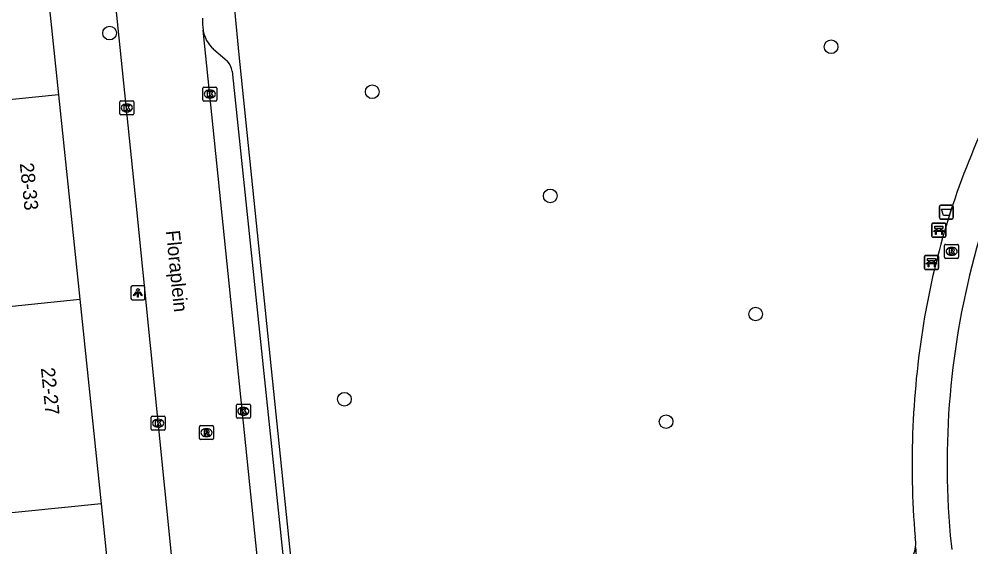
# Model space of a CAD drawing. Extents: x 162250 to 162654, y 380744 to 381605.
# Drawn here: x 162546.8 to 162615, y 380793.8 to 380831.6 of the extents above; entities that cross this region are included whole.
import ezdxf

# ---------------------------------------------------------------- set-up
doc = ezdxf.new("R2010")
doc.units = 0
for name, color, linetype in [('IMGEO_Afvalbak', 7, 'Continuous'), ('IMGEO_Bank', 7, 'Continuous'), ('IMGEO_Boom', 7, 'Continuous'), ('IMGEO_Fietspad_gesloten', 7, 'Continuous'), ('IMGEO_Kolk', 7, 'Continuous'), ('IMGEO_Lichtpunt', 7, 'Continuous'), ('IMGEO_Openbare_ruimte_label', 7, 'Continuous'), ('IMGEO_Pand', 7, 'Continuous'), ('IMGEO_Pand_nummerreeks', 7, 'Continuous'), ('IMGEO_Rijbaan_lokaal_open', 7, 'Continuous'), ('IMGEO_Rioolput', 7, 'Continuous'), ('IMGEO_Voetpad_open', 7, 'Continuous')]:
    doc.layers.add(name, color=color, linetype=linetype)

msp = doc.modelspace()

# ---------------------------------------------------------------- linework, layer by layer
at = {"layer": 'IMGEO_Afvalbak'}
for p, q in [((162612.693, 380817.38), (162612.693, 380818.18)), ((162612.693, 380818.18), (162612.693, 380817.38)), ((162612.793, 380818.28), (162613.583, 380818.28)), ((162613.583, 380818.28), (162612.793, 380818.28)), ((162613.683, 380818.18), (162613.683, 380817.38)), ((162613.683, 380817.38), (162613.683, 380818.18)), ((162613.583, 380817.28), (162612.793, 380817.28)), ((162612.793, 380817.28), (162613.583, 380817.28))]:
    msp.add_line(p, q, dxfattribs=at)
msp.add_lwpolyline([(162612.836, 380817.994), (162613.54, 380817.994), (162613.391, 380817.524), (162612.985, 380817.524), (162612.836, 380817.994)], dxfattribs=at)
for centre, start, end in [((162612.793, 380818.18), 90, 180), ((162612.793, 380818.18), 90, 180), ((162613.583, 380818.18), 0, 90), ((162613.583, 380818.18), 360, 90), ((162612.793, 380817.38), 180, 270), ((162612.793, 380817.38), 180, 270), ((162613.583, 380817.38), 270, 0), ((162613.583, 380817.38), 270, 0)]:
    msp.add_arc(centre, 0.1, start, end, dxfattribs=at)
at = {"layer": 'IMGEO_Bank'}
for p, q in [((162612.153, 380816.06), (162612.153, 380816.901)), ((162612.153, 380816.901), (162612.153, 380816.06)), ((162612.228, 380816.985), (162613.069, 380816.985)), ((162613.069, 380816.985), (162612.228, 380816.985)), ((162613.153, 380816.91), (162613.153, 380816.069)), ((162613.153, 380816.069), (162613.153, 380816.91)), ((162612.85, 380816.383), (162612.457, 380816.383)), ((162612.462, 380816.491), (162612.462, 380816.597)), ((162612.506, 380816.597), (162612.506, 380816.491)), ((162612.794, 380816.603), (162612.512, 380816.603)), ((162612.512, 380816.485), (162612.794, 380816.485)), ((162612.8, 380816.491), (162612.8, 380816.597)), ((162612.844, 380816.597), (162612.844, 380816.491)), ((162613.078, 380815.985), (162612.237, 380815.985)), ((162612.237, 380815.985), (162613.078, 380815.985)), ((162611.627, 380813.752), (162611.627, 380814.593)), ((162611.627, 380814.593), (162611.627, 380813.752)), ((162611.702, 380814.677), (162612.543, 380814.677)), ((162612.543, 380814.677), (162611.702, 380814.677)), ((162612.324, 380814.075), (162611.931, 380814.075)), ((162611.936, 380814.183), (162611.936, 380814.289)), ((162611.98, 380814.289), (162611.98, 380814.183)), ((162612.268, 380814.295), (162611.986, 380814.295)), ((162611.986, 380814.177), (162612.268, 380814.177)), ((162612.274, 380814.183), (162612.274, 380814.289)), ((162612.318, 380814.289), (162612.318, 380814.183)), ((162612.627, 380814.602), (162612.627, 380813.761)), ((162612.627, 380813.761), (162612.627, 380814.602)), ((162612.552, 380813.677), (162611.711, 380813.677)), ((162611.711, 380813.677), (162612.552, 380813.677))]:
    msp.add_line(p, q, dxfattribs=at)
for points in [[(162612.4, 380816.383), (162612.258, 380816.383), (162612.37, 380816.485), (162612.456, 380816.485)], [(162612.456, 380816.603), (162612.37, 380816.603), (162612.37, 380816.764), (162612.933, 380816.764), (162612.933, 380816.603), (162612.85, 380816.603)], [(162612.45, 380816.376), (162612.45, 380816.169), (162612.407, 380816.169), (162612.407, 380816.376)], [(162612.85, 380816.485), (162612.933, 380816.485), (162613.045, 380816.383), (162612.906, 380816.383)], [(162612.9, 380816.376), (162612.9, 380816.169), (162612.856, 380816.169), (162612.856, 380816.376)], [(162611.874, 380814.075), (162611.732, 380814.075), (162611.844, 380814.177), (162611.93, 380814.177)], [(162611.93, 380814.295), (162611.844, 380814.295), (162611.844, 380814.456), (162612.407, 380814.456), (162612.407, 380814.295), (162612.324, 380814.295)], [(162611.924, 380814.068), (162611.924, 380813.861), (162611.881, 380813.861), (162611.881, 380814.068)], [(162612.324, 380814.177), (162612.407, 380814.177), (162612.519, 380814.075), (162612.38, 380814.075)], [(162612.374, 380814.068), (162612.374, 380813.861), (162612.33, 380813.861), (162612.33, 380814.068)]]:
    msp.add_lwpolyline(points, dxfattribs=at)
for centre, radius, start, end in [((162612.231, 380816.907), 0.0779, 92.4484, 184.28452), ((162612.231, 380816.907), 0.0779, 92.4484, 184.28452), ((162613.075, 380816.907), 0.0779, 2.4484, 94.28452), ((162613.075, 380816.907), 0.0779, 2.4484, 94.28452), ((162612.4, 380816.376), 0.00671, 2.89567, 87.10433), ((162612.457, 380816.376), 0.00671, 92.89567, 177.10433), ((162612.455, 380816.596), 0.00671, 2.89567, 87.10433), ((162612.455, 380816.492), 0.00671, 272.89567, 357.10433), ((162612.512, 380816.596), 0.00671, 92.89567, 177.10433), ((162612.512, 380816.492), 0.00671, 182.89567, 267.10433), ((162612.794, 380816.596), 0.00671, 2.89567, 87.10433), ((162612.794, 380816.492), 0.00671, 272.89567, 357.10433), ((162612.851, 380816.596), 0.00671, 92.89567, 177.10433), ((162612.851, 380816.492), 0.00671, 182.89567, 267.10433), ((162612.849, 380816.376), 0.00671, 2.89567, 87.10433), ((162612.906, 380816.376), 0.00671, 92.89567, 177.10433), ((162612.231, 380816.063), 0.0779, 182.4484, 274.28452), ((162612.231, 380816.063), 0.0779, 182.4484, 274.28452), ((162613.075, 380816.063), 0.0779, 272.4484, 4.28452), ((162613.075, 380816.063), 0.0779, 272.4484, 4.28452), ((162611.705, 380814.599), 0.0779, 92.4484, 184.28452), ((162611.705, 380814.599), 0.0779, 92.4484, 184.28452), ((162611.874, 380814.068), 0.00671, 2.89567, 87.10433), ((162611.931, 380814.068), 0.00671, 92.89567, 177.10433), ((162611.929, 380814.288), 0.00671, 2.89567, 87.10433), ((162611.929, 380814.184), 0.00671, 272.89567, 357.10433), ((162611.986, 380814.288), 0.00671, 92.89567, 177.10433), ((162611.986, 380814.184), 0.00671, 182.89567, 267.10433), ((162612.268, 380814.288), 0.00671, 2.89567, 87.10433), ((162612.268, 380814.184), 0.00671, 272.89567, 357.10433), ((162612.325, 380814.288), 0.00671, 92.89567, 177.10433), ((162612.325, 380814.184), 0.00671, 182.89567, 267.10433), ((162612.323, 380814.068), 0.00671, 2.89567, 87.10433), ((162612.38, 380814.068), 0.00671, 92.89567, 177.10433), ((162612.549, 380814.599), 0.0779, 2.4484, 94.28452), ((162612.549, 380814.599), 0.0779, 2.4484, 94.28452), ((162611.705, 380813.755), 0.0779, 182.4484, 274.28452), ((162611.705, 380813.755), 0.0779, 182.4484, 274.28452), ((162612.549, 380813.755), 0.0779, 272.4484, 4.28452), ((162612.549, 380813.755), 0.0779, 272.4484, 4.28452)]:
    msp.add_arc(centre, radius, start, end, dxfattribs=at)
at = {"layer": 'IMGEO_Boom'}
for centre in [(162553.294, 380830.584), (162604.942, 380829.605), (162572.094, 380826.386), (162584.831, 380818.936), (162599.539, 380810.487), (162570.107, 380804.394), (162593.129, 380802.787)]:
    msp.add_circle(centre, 0.489, dxfattribs=at)
at = {"layer": 'IMGEO_Fietspad_gesloten'}
msp.add_lwpolyline([(162613.473, 380794.639), (162613.577, 380793.648)], dxfattribs=at)
msp.add_arc((162670.749, 380799.765), 57.505, 163.75865, 185.11392, dxfattribs=at)
at = {"layer": 'IMGEO_Kolk'}
for p, q in [((162559.968, 380825.795), (162559.968, 380826.647)), ((162560.043, 380826.721), (162560.895, 380826.721)), ((162560.456, 380826.501), (162560.481, 380826.501)), ((162560.969, 380826.647), (162560.969, 380825.795)), ((162554.023, 380824.802), (162554.023, 380825.654)), ((162554.098, 380825.728), (162554.95, 380825.728)), ((162555.024, 380825.654), (162555.024, 380824.802)), ((162560.895, 380825.721), (162560.043, 380825.721)), ((162560.479, 380825.941), (162560.454, 380825.941)), ((162554.511, 380825.508), (162554.536, 380825.508)), ((162554.95, 380824.728), (162554.098, 380824.728)), ((162554.534, 380824.948), (162554.509, 380824.948)), ((162562.366, 380803.104), (162562.366, 380803.956)), ((162562.441, 380804.03), (162563.293, 380804.03)), ((162563.367, 380803.956), (162563.367, 380803.104)), ((162556.342, 380803.175), (162557.194, 380803.175)), ((162562.877, 380803.25), (162562.852, 380803.25)), ((162562.854, 380803.81), (162562.879, 380803.81)), ((162556.267, 380802.249), (162556.267, 380803.101)), ((162556.755, 380802.955), (162556.78, 380802.955)), ((162557.268, 380803.101), (162557.268, 380802.249)), ((162563.293, 380803.03), (162562.441, 380803.03)), ((162557.194, 380802.175), (162556.342, 380802.175)), ((162556.778, 380802.395), (162556.753, 380802.395))]:
    msp.add_line(p, q, dxfattribs=at)
for points in [[(162559.968, 380825.795), (162559.968, 380826.647)], [(162560.043, 380826.721), (162560.895, 380826.721)], [(162560.289, 380826.421), (162560.412, 380826.421), (162560.412, 380826.27), (162560.542, 380826.421), (162560.706, 380826.421), (162560.56, 380826.27), (162560.713, 380826.021), (162560.561, 380826.021), (162560.476, 380826.185), (162560.412, 380826.118), (162560.412, 380826.021), (162560.289, 380826.021), (162560.289, 380826.421)], [(162560.969, 380826.647), (162560.969, 380825.795)], [(162554.023, 380824.802), (162554.023, 380825.654)], [(162554.098, 380825.728), (162554.95, 380825.728)], [(162555.024, 380825.654), (162555.024, 380824.802)], [(162560.895, 380825.721), (162560.043, 380825.721)], [(162554.344, 380825.428), (162554.467, 380825.428), (162554.467, 380825.277), (162554.597, 380825.428), (162554.761, 380825.428), (162554.615, 380825.277), (162554.768, 380825.028), (162554.616, 380825.028), (162554.531, 380825.192), (162554.467, 380825.125), (162554.467, 380825.028), (162554.344, 380825.028), (162554.344, 380825.428)], [(162554.95, 380824.728), (162554.098, 380824.728)], [(162562.366, 380803.104), (162562.366, 380803.956)], [(162562.441, 380804.03), (162563.293, 380804.03)], [(162563.367, 380803.956), (162563.367, 380803.104)], [(162556.342, 380803.175), (162557.194, 380803.175)], [(162562.687, 380803.73), (162562.81, 380803.73), (162562.81, 380803.579), (162562.94, 380803.73), (162563.104, 380803.73), (162562.958, 380803.579), (162563.111, 380803.33), (162562.959, 380803.33), (162562.874, 380803.494), (162562.81, 380803.427), (162562.81, 380803.33), (162562.687, 380803.33), (162562.687, 380803.73)], [(162556.267, 380802.249), (162556.267, 380803.101)], [(162556.588, 380802.875), (162556.711, 380802.875), (162556.711, 380802.724), (162556.841, 380802.875), (162557.005, 380802.875), (162556.859, 380802.724), (162557.012, 380802.475), (162556.86, 380802.475), (162556.775, 380802.639), (162556.711, 380802.572), (162556.711, 380802.475), (162556.588, 380802.475), (162556.588, 380802.875)], [(162557.268, 380803.101), (162557.268, 380802.249)], [(162563.293, 380803.03), (162562.441, 380803.03)], [(162557.194, 380802.175), (162556.342, 380802.175)]]:
    msp.add_lwpolyline(points, dxfattribs=at)
for centre, start, end in [((162560.045, 380826.645), 91.55205, 178.44795), ((162560.045, 380826.645), 91.55205, 178.44795), ((162560.893, 380826.645), 1.55205, 88.44795), ((162560.893, 380826.645), 1.55205, 88.44795), ((162554.1, 380825.652), 91.55205, 178.44795), ((162554.1, 380825.652), 91.55205, 178.44795), ((162554.948, 380825.652), 1.55205, 88.44795), ((162554.948, 380825.652), 1.55205, 88.44795), ((162560.045, 380825.797), 181.55205, 268.44795), ((162560.045, 380825.797), 181.55205, 268.44795), ((162560.893, 380825.797), 271.55205, 358.44795), ((162560.893, 380825.797), 271.55205, 358.44795), ((162554.1, 380824.804), 181.55205, 268.44795), ((162554.1, 380824.804), 181.55205, 268.44795), ((162554.948, 380824.804), 271.55205, 358.44795), ((162554.948, 380824.804), 271.55205, 358.44795), ((162562.443, 380803.954), 91.55205, 178.44795), ((162562.443, 380803.954), 91.55205, 178.44795), ((162563.291, 380803.954), 1.55205, 88.44795), ((162563.291, 380803.954), 1.55205, 88.44795), ((162556.344, 380803.099), 91.55205, 178.44795), ((162556.344, 380803.099), 91.55205, 178.44795), ((162557.192, 380803.099), 1.55205, 88.44795), ((162557.192, 380803.099), 1.55205, 88.44795), ((162562.443, 380803.106), 181.55205, 268.44795), ((162562.443, 380803.106), 181.55205, 268.44795), ((162563.291, 380803.106), 271.55205, 358.44795), ((162563.291, 380803.106), 271.55205, 358.44795), ((162556.344, 380802.251), 181.55205, 268.44795), ((162556.344, 380802.251), 181.55205, 268.44795), ((162557.192, 380802.251), 271.55205, 358.44795), ((162557.192, 380802.251), 271.55205, 358.44795)]:
    msp.add_arc(centre, 0.0765, start, end, dxfattribs=at)
for centre, major_axis, ratio, start_param, end_param in [((162560.455, 380826.221), (-0.387, 0.002), 0.722429, 4.712389, 7.853982), ((162560.48, 380826.221), (-0.39, 0.002), 0.717154, 1.570796, 4.712389), ((162554.51, 380825.228), (-0.387, 0.002), 0.722429, 4.712389, 7.853982), ((162554.535, 380825.228), (-0.39, 0.002), 0.717154, 1.570796, 4.712389), ((162562.853, 380803.53), (-0.387, 0.002), 0.722429, 4.712389, 7.853982), ((162562.878, 380803.53), (-0.39, 0.002), 0.717154, 1.570796, 4.712389), ((162556.754, 380802.675), (-0.387, 0.002), 0.722429, 4.712389, 7.853982), ((162556.779, 380802.675), (-0.39, 0.002), 0.717154, 1.570796, 4.712389)]:
    msp.add_ellipse(centre, major_axis=major_axis, ratio=ratio, start_param=start_param, end_param=end_param, dxfattribs=at)
at = {"layer": 'IMGEO_Lichtpunt'}
for p, q in [((162554.824, 380812.406), (162554.824, 380811.599)), ((162554.824, 380812.406), (162554.824, 380811.599)), ((162555.726, 380812.501), (162554.918, 380812.501)), ((162555.726, 380812.501), (162554.918, 380812.501)), ((162555.82, 380811.599), (162555.82, 380812.406)), ((162555.82, 380811.599), (162555.82, 380812.406)), ((162554.918, 380811.505), (162555.726, 380811.505)), ((162554.918, 380811.505), (162555.726, 380811.505))]:
    msp.add_line(p, q, dxfattribs=at)
for points in [[(162555.198, 380812.07), (162555.237, 380812.042), (162555.049, 380811.78), (162555.011, 380811.807), (162555.198, 380812.07)], [(162555.3, 380812.022), (162555.347, 380812.022), (162555.347, 380811.7), (162555.3, 380811.7), (162555.3, 380812.022)], [(162555.41, 380812.042), (162555.448, 380812.069), (162555.635, 380811.807), (162555.596, 380811.779), (162555.41, 380812.042)]]:
    msp.add_lwpolyline(points, dxfattribs=at)
msp.add_circle((162555.323, 380812.204), 0.0994, dxfattribs=at)
for centre, start, end in [((162554.918, 380812.406), 90, 180), ((162554.918, 380812.406), 90, 180), ((162555.726, 380812.406), 0, 90), ((162555.726, 380812.406), 0, 90), ((162554.918, 380811.599), 180, 270), ((162554.918, 380811.599), 180, 270), ((162555.726, 380811.599), 270, 0), ((162555.726, 380811.599), 270, 360)]:
    msp.add_arc(centre, 0.0946, start, end, dxfattribs=at)
at = {"layer": 'IMGEO_Pand'}
for points in [[(162548.112, 380840.779), (162549.634, 380826.158)], [(162549.634, 380826.158), (162538.803, 380825.063)], [(162549.634, 380826.158), (162551.156, 380811.537)], [(162540.295, 380810.439), (162551.156, 380811.537)], [(162551.156, 380811.537), (162552.678, 380796.916)], [(162552.678, 380796.916), (162541.786, 380795.815)], [(162552.678, 380796.916), (162554.2, 380782.295)]]:
    msp.add_lwpolyline(points, dxfattribs=at)
at = {"layer": 'IMGEO_Rijbaan_lokaal_open'}
for points in [[(162558.777, 380782.848), (162555.189, 380818.45), (162553.575, 380834.204), (162551.932, 380848.95), (162551.063, 380856.512), (162550.999, 380857.103)], [(162565.117, 380780.89), (162559.982, 380830.788)]]:
    msp.add_lwpolyline(points, dxfattribs=at)
msp.add_arc((162566.086, 380831.46), 6.14, 178.25992, 186.27863, dxfattribs=at)
at = {"layer": 'IMGEO_Rioolput'}
for p, q in [((162613.141, 380815.469), (162613.993, 380815.469)), ((162613.066, 380814.543), (162613.066, 380815.395)), ((162613.554, 380815.249), (162613.579, 380815.249)), ((162614.067, 380815.395), (162614.067, 380814.543)), ((162613.993, 380814.469), (162613.141, 380814.469)), ((162613.577, 380814.689), (162613.552, 380814.689)), ((162559.801, 380802.502), (162560.653, 380802.502)), ((162559.726, 380801.576), (162559.726, 380802.428)), ((162560.214, 380802.282), (162560.239, 380802.282)), ((162560.727, 380802.428), (162560.727, 380801.576)), ((162560.653, 380801.502), (162559.801, 380801.502)), ((162560.237, 380801.722), (162560.212, 380801.722))]:
    msp.add_line(p, q, dxfattribs=at)
for points in [[(162613.141, 380815.469), (162613.993, 380815.469)], [(162613.066, 380814.543), (162613.066, 380815.395)], [(162613.655, 380815.167), (162613.403, 380815.169), (162613.403, 380814.769)], [(162613.403, 380814.769), (162613.527, 380814.769), (162613.527, 380814.931), (162613.538, 380814.931)], [(162613.581, 380815.088), (162613.527, 380815.088), (162613.527, 380815.007)], [(162613.527, 380815.007), (162613.579, 380815.007)], [(162613.585, 380814.902), (162613.656, 380814.769), (162613.796, 380814.769), (162613.731, 380814.895)], [(162614.067, 380815.395), (162614.067, 380814.543)], [(162613.993, 380814.469), (162613.141, 380814.469)], [(162559.801, 380802.502), (162560.653, 380802.502)], [(162559.726, 380801.576), (162559.726, 380802.428)], [(162560.315, 380802.2), (162560.063, 380802.202), (162560.063, 380801.802)], [(162560.063, 380801.802), (162560.187, 380801.802), (162560.187, 380801.964), (162560.198, 380801.964)], [(162560.241, 380802.121), (162560.187, 380802.121), (162560.187, 380802.04)], [(162560.187, 380802.04), (162560.239, 380802.04)], [(162560.245, 380801.935), (162560.316, 380801.802), (162560.456, 380801.802), (162560.391, 380801.928)], [(162560.727, 380802.428), (162560.727, 380801.576)], [(162560.653, 380801.502), (162559.801, 380801.502)]]:
    msp.add_lwpolyline(points, dxfattribs=at)
for centre, radius, start, end in [((162613.143, 380815.393), 0.0765, 91.55205, 178.44795), ((162613.143, 380815.393), 0.0765, 91.55205, 178.44795), ((162613.991, 380815.393), 0.0765, 1.55205, 88.44795), ((162613.991, 380815.393), 0.0765, 1.55205, 88.44795), ((162613.537, 380814.878), 0.0533, 26.02933, 88.69889), ((162613.563, 380815.196), 0.19, 274.7715, 282.96867), ((162613.587, 380814.992), 0.0964, 77.00612, 93.18647), ((162613.601, 380815.049), 0.0378, 276.66336, 79.67722), ((162613.654, 380815.057), 0.109, 350.36119, 89.41601), ((162613.652, 380815.057), 0.112, 277.58423, 350.98172), ((162613.636, 380814.842), 0.108, 29.51342, 73.79051), ((162613.143, 380814.545), 0.0765, 181.55205, 268.44795), ((162613.143, 380814.545), 0.0765, 181.55205, 268.44795), ((162613.991, 380814.545), 0.0765, 271.55205, 358.44795), ((162613.991, 380814.545), 0.0765, 271.55205, 358.44795), ((162559.803, 380802.426), 0.0765, 91.55205, 178.44795), ((162559.803, 380802.426), 0.0765, 91.55205, 178.44795), ((162560.651, 380802.426), 0.0765, 1.55205, 88.44795), ((162560.651, 380802.426), 0.0765, 1.55205, 88.44795), ((162560.197, 380801.911), 0.0533, 26.02933, 88.69889), ((162560.223, 380802.229), 0.19, 274.7715, 282.96867), ((162560.247, 380802.025), 0.0964, 77.00612, 93.18647), ((162560.261, 380802.082), 0.0378, 276.66336, 79.67722), ((162560.314, 380802.09), 0.109, 350.36119, 89.41601), ((162560.312, 380802.09), 0.112, 277.58423, 350.98172), ((162560.296, 380801.875), 0.108, 29.51342, 73.79051), ((162559.803, 380801.578), 0.0765, 181.55205, 268.44795), ((162559.803, 380801.578), 0.0765, 181.55205, 268.44795), ((162560.651, 380801.578), 0.0765, 271.55205, 358.44795), ((162560.651, 380801.578), 0.0765, 271.55205, 358.44795)]:
    msp.add_arc(centre, radius, start, end, dxfattribs=at)
for centre, major_axis, ratio, start_param, end_param in [((162613.553, 380814.969), (-0.387, 0.002), 0.722429, 4.712389, 7.853982), ((162613.578, 380814.969), (-0.39, 0.002), 0.717154, 1.570796, 4.712389), ((162560.213, 380802.002), (-0.387, 0.002), 0.722429, 4.712389, 7.853982), ((162560.238, 380802.002), (-0.39, 0.002), 0.717154, 1.570796, 4.712389)]:
    msp.add_ellipse(centre, major_axis=major_axis, ratio=ratio, start_param=start_param, end_param=end_param, dxfattribs=at)
at = {"layer": 'IMGEO_Voetpad_open'}
for points in [[(162567.473, 380781.301), (162567.093, 380785.029), (162562.571, 380829.016), (162562.247, 380832.277), (162567.053, 380833.21), (162567.066, 380833.212), (162567.19, 380832.512), (162568.517, 380832.81)], [(162560.718, 380829.445), (162561.737, 380828.562)], [(162562.062, 380827.851), (162562.206, 380826.468), (162566.637, 380784.181)], [(162610.982, 380793.826), (162611.277, 380789.905)]]:
    msp.add_lwpolyline(points, dxfattribs=at)
for centre, radius, start, end in [((162562.343, 380831.209), 2.398, 190.10246, 227.34538), ((162560.746, 380827.679), 1.328, 7.44321, 41.68733), ((162666.461, 380800.728), 55.656, 154.17751, 170.10843), ((162673.375, 380799.739), 62.637, 170.30334, 184.76931), ((162608.724, 380794.093), 2.273, 353.266, 11.12047), ((162608.73, 380794.095), 2.268, 290.32754, 353.2002)]:
    msp.add_arc(centre, radius, start, end, dxfattribs=at)

# ---------------------------------------------------------------- texts
at = {"layer": 'IMGEO_Openbare_ruimte_label'}
msp.add_text('Floraplein', height=1, rotation=275.7391, dxfattribs=at).set_placement((162557.323, 380816.429))
at = {"layer": 'IMGEO_Pand_nummerreeks'}
for s, rotation, p in [('28-33', 275.94686, (162546.859, 380821.257)), ('22-27', 275.79525, (162548.372, 380806.612))]:
    msp.add_text(s, height=1, rotation=rotation, dxfattribs=at).set_placement(p)

doc.saveas('drawing.dxf')
